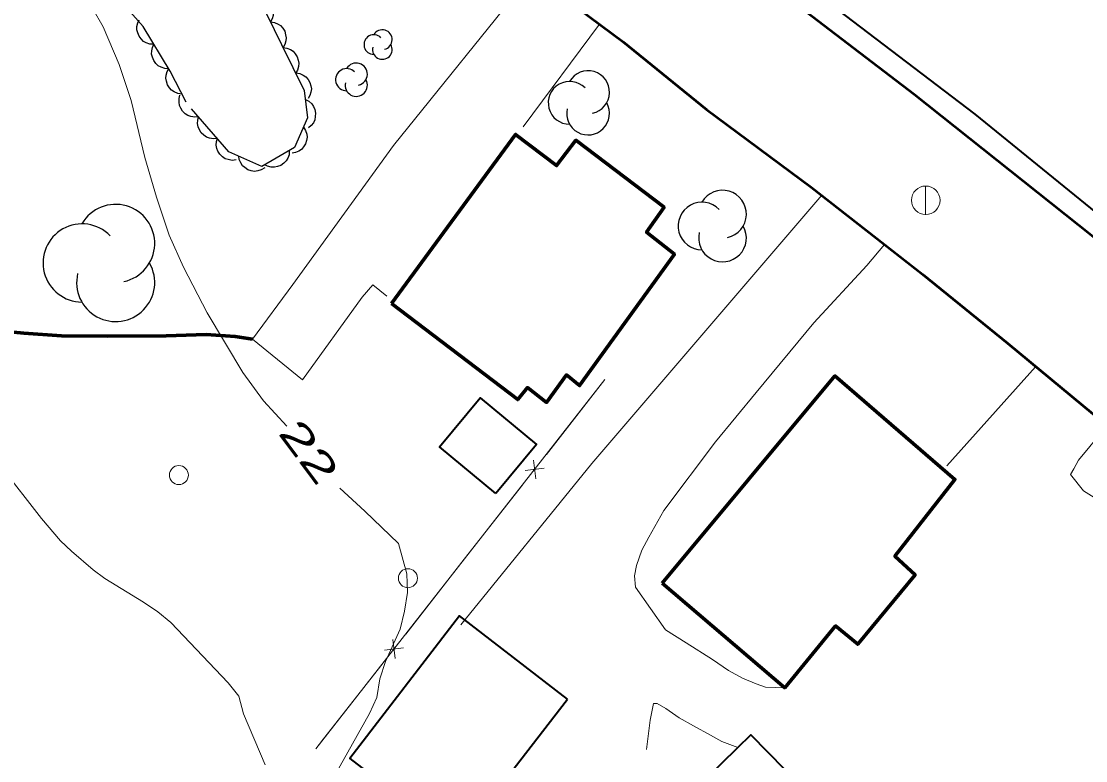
# Model space of a CAD drawing. Extents: x 356765 to 358572, y 5103174 to 5104650.
# Drawn here: x 357573.2 to 357629.2, y 5103650.7 to 5103689.6 of the extents above; entities that cross this region are included whole.
import ezdxf
from ezdxf.enums import TextEntityAlignment as Align

# ---------------------------------------------------------------- set-up
doc = ezdxf.new("R2010")
doc.units = 0
doc.header["$LTSCALE"] = 0.6
doc.linetypes.add('DOT_DASHED', pattern=[7.7, 5, -1.2, 0.3, -1.2])
doc.linetypes.add('LONG_DASHED', pattern=[7.5, 6, -1.5])
for name, color, linetype, lineweight in [('19', 7, 'Continuous', 13), ('2', 7, 'Continuous', 13), ('21', 7, 'Continuous', 53), ('22', 7, 'Continuous', 35), ('31', 7, 'Continuous', 70), ('36', 7, 'Continuous', 13), ('37', 7, 'Continuous', 13), ('44', 7, 'Continuous', 25)]:
    doc.layers.add(name, color=color, linetype=linetype, lineweight=lineweight)

msp = doc.modelspace()

# ---------------------------------------------------------------- linework, layer by layer
at = {"layer": '19'}
for p, q in [((357603.65, 5103689.44), (357599.62, 5103684.05)), ((357621.91, 5103666.22), (357626.58, 5103671.42))]:
    msp.add_line(p, q, dxfattribs=at)
for points in [[(357600.09, 5103692.09), (357592.81, 5103683.07), (357587.51, 5103675.75), (357585.39, 5103672.87), (357588.01, 5103670.74), (357591.15, 5103675.08), (357591.71, 5103675.74), (357592.45, 5103675.14)], [(357615.33, 5103680.45), (357603.23, 5103666.34), (357596.34, 5103657.85)], [(357618.63, 5103677.86), (357617.7, 5103676.76), (357614.92, 5103673.73), (357611.89, 5103670.07), (357609.75, 5103667.48), (357607.03, 5103663.87), (357606.24, 5103662.46), (357605.86, 5103661.79), (357605.59, 5103660.97), (357605.49, 5103660.44), (357605.54, 5103659.83), (357607.12, 5103657.59), (357608.2, 5103656.9), (357609.58, 5103656.03), (357610.43, 5103655.46), (357611.17, 5103655.05), (357611.89, 5103654.75), (357612.38, 5103654.57), (357613.39, 5103654.55)], [(357630.35, 5103668.35), (357629.44, 5103667.24), (357628.84, 5103666.51), (357628.59, 5103666.06), (357628.42, 5103665.77), (357629.11, 5103664.9), (357630.56, 5103663.99), (357630.72, 5103664.1), (357630.99, 5103664.24), (357631.65, 5103665.23), (357632.63, 5103666.4)], [(357610.92, 5103651.4), (357610.07, 5103651.72), (357609.48, 5103652.05), (357608.58, 5103652.55), (357607.84, 5103652.97), (357607.13, 5103653.46), (357606.68, 5103653.71), (357606.49, 5103653.72), (357606.3, 5103652.85), (357606.12, 5103651.3)]]:
    msp.add_lwpolyline(points, dxfattribs=at)
at = {"layer": '2'}
for points in [[(357587.19, 5103668.3), (357585.97, 5103669.63), (357584.88, 5103671.12), (357583.01, 5103674.26), (357581.75, 5103676.67), (357581, 5103678.34), (357580.34, 5103680.34), (357579.73, 5103682.44), (357579.01, 5103685.43), (357578.38, 5103687.33), (357577.53, 5103689.3), (357576.99, 5103690.25)], [(357586.06, 5103650.5), (357584.92, 5103653.17), (357584.66, 5103654.1), (357584.11, 5103654.8), (357581.09, 5103657.97), (357580.4, 5103658.54), (357579.66, 5103659.05), (357577.61, 5103660.3), (357577.01, 5103660.75), (357575.86, 5103661.73), (357575.29, 5103662.28), (357574.29, 5103663.44), (357572.13, 5103666.22)], [(357587.96, 5103646.82), (357591.54, 5103653.19), (357591.92, 5103654.04), (357592.08, 5103655.02), (357592.39, 5103655.92), (357593.15, 5103657.63), (357593.39, 5103658.57), (357593.54, 5103659.55), (357593.51, 5103660.54), (357593.06, 5103662.13), (357591.3, 5103663.84), (357589.98, 5103665.05)]]:
    msp.add_lwpolyline(points, dxfattribs=at)
at = {"layer": '21'}
for points in [[(357597.8, 5103693.8), (357604.89, 5103688.51), (357609.27, 5103684.96), (357614.77, 5103680.88), (357618.63, 5103677.86), (357620.65, 5103676.28), (357625.11, 5103672.66), (357629.6, 5103668.96), (357630.35, 5103668.35), (357631.55, 5103667.41), (357632.63, 5103666.4), (357636.95, 5103662.44), (357642.39, 5103657.42), (357648.4, 5103651.88), (357652.86, 5103647.7), (357660.15, 5103641.04), (357668.64, 5103633.26), (357674.75, 5103627.69), (357683.46, 5103619.66), (357688.82, 5103614.49), (357695.55, 5103608.21), (357701.4, 5103602.98), (357707.92, 5103596.9)], [(357609.42, 5103694), (357620.2, 5103685.76), (357630.29, 5103677.74), (357638.22, 5103670.75), (357649.79, 5103660.22), (357666.81, 5103644.4), (357691.49, 5103621.57), (357705.7, 5103608.53), (357720.27, 5103594.97), (357725.87, 5103589.74), (357737.61, 5103580.01), (357753.29, 5103566.65), (357772.09, 5103550.34), (357790.98, 5103533.8), (357803.11, 5103523.29), (357815.96, 5103512.34), (357841.89, 5103502.09), (357843.77, 5103501.5), (357845.45, 5103501.88), (357846.53, 5103502.66), (357866.19, 5103521.97)]]:
    msp.add_lwpolyline(points, dxfattribs=at)
at = {"layer": '22'}
msp.add_lwpolyline([(357610.19, 5103694.78), (357623.39, 5103684.71), (357633.04, 5103676.88), (357640.64, 5103670.23), (357649.82, 5103661.72), (357659.7, 5103652.78)], dxfattribs=at)
at = {"layer": '22', "linetype": 'LONG_DASHED', "lineweight": 70}
msp.add_lwpolyline([(357585.39, 5103672.87), (357584.48, 5103673.02), (357582.95, 5103673.12), (357580.84, 5103673.05), (357577.78, 5103673.03), (357575.33, 5103673.06), (357573.35, 5103673.19), (357569.8, 5103673.54), (357568.62, 5103673.71), (357567.22, 5103674), (357565.74, 5103674.34), (357564.38, 5103674.71), (357562.13, 5103675.57), (357557.66, 5103677.38), (357556.05, 5103678.18), (357553.84, 5103679.31), (357551.09, 5103680.82), (357548.78, 5103682.11), (357547.03, 5103683.18), (357544.91, 5103684.46), (357542.78, 5103685.74), (357540.55, 5103687.17), (357537.33, 5103689.29)], dxfattribs=at)
at = {"layer": '31'}
for points in [[(357592.7, 5103674.76), (357599.34, 5103669.7), (357599.85, 5103670.33), (357600.86, 5103669.55), (357601.9, 5103671), (357602.59, 5103670.44), (357607.58, 5103677.34), (357606.12, 5103678.5), (357607.04, 5103679.82), (357602.4, 5103683.34), (357601.38, 5103682.01), (357599.23, 5103683.65), (357592.7, 5103674.76)], [(357606.94, 5103660.04), (357616.03, 5103670.95), (357622.34, 5103665.5), (357619.18, 5103661.46), (357620.24, 5103660.48), (357617.23, 5103656.83), (357616.06, 5103657.8), (357613.39, 5103654.55), (357606.94, 5103660.04)]]:
    msp.add_lwpolyline(points, close=True, dxfattribs=at)
at = {"layer": '31', "lineweight": 35}
for points in [[(357598.18, 5103664.76), (357595.22, 5103667.22), (357597.36, 5103669.8), (357600.32, 5103667.34), (357598.18, 5103664.76)], [(357601.95, 5103653.95), (357596.28, 5103658.32), (357590.51, 5103650.82), (357596.18, 5103646.46), (357601.95, 5103653.95)], [(357620.04, 5103638.04), (357613.64, 5103644.54), (357613.07, 5103643.97), (357608.29, 5103648.82), (357610.92, 5103651.4), (357611.6, 5103652.07), (357616.03, 5103647.57), (357618.13, 5103649.63), (357624.87, 5103642.79), (357620.04, 5103638.04)]]:
    msp.add_lwpolyline(points, close=True, dxfattribs=at)
at = {"layer": '36'}
msp.add_line((357620.8, 5103679.42), (357620.8, 5103680.92), dxfattribs=at)
for centre, radius in [((357620.8055, 5103680.1813), 0.75), ((357581.5148, 5103665.7306), 0.5), ((357593.5638, 5103660.3071), 0.5)]:
    msp.add_circle(centre, radius, dxfattribs=at)
at = {"layer": '37'}
for p, q in [((357603.93, 5103670.75), (357588.72, 5103651.33)), ((357603.93, 5103670.75), (357600.85, 5103666.81)), ((357600.17, 5103666.52), (357600.29, 5103665.53)), ((357599.73, 5103665.97), (357600.73, 5103666.09)), ((357599.61, 5103665.24), (357596.53, 5103661.3)), ((357596.53, 5103661.3), (357593.45, 5103657.37)), ((357592.33, 5103656.52), (357593.33, 5103656.64)), ((357592.77, 5103657.08), (357592.89, 5103656.08)), ((357592.21, 5103655.79), (357589.13, 5103651.86)), ((357589.13, 5103651.86), (357588.72, 5103651.33))]:
    msp.add_line(p, q, dxfattribs=at)
at = {"layer": '44', "linetype": 'DOT_DASHED'}
msp.add_lwpolyline([(357585.73, 5103690.79), (357586.92, 5103688.38), (357588.11, 5103685.96), (357588.28, 5103684.51), (357587.6, 5103682.95), (357585.87, 5103681.96), (357584.15, 5103682.73), (357581.89, 5103685.34), (357581.05, 5103686.98), (357579.63, 5103689.33), (357575.92, 5103693.53)], dxfattribs=at)
at = {"layer": '44'}
for points in [[(357585.67, 5103690.91), (357585.88, 5103690.88), (357586.06, 5103690.8), (357586.2, 5103690.71), (357586.32, 5103690.58), (357586.41, 5103690.42), (357586.47, 5103690.24), (357586.5, 5103690.08), (357586.48, 5103689.9), (357586.42, 5103689.72), (357586.33, 5103689.57)], [(357580.2, 5103688.39), (357579.99, 5103688.4), (357579.8, 5103688.47), (357579.65, 5103688.54), (357579.53, 5103688.67), (357579.42, 5103688.81), (357579.35, 5103688.99), (357579.3, 5103689.15), (357579.31, 5103689.33), (357579.35, 5103689.51), (357579.42, 5103689.67)], [(357586.33, 5103689.57), (357586.54, 5103689.54), (357586.73, 5103689.45), (357586.86, 5103689.37), (357586.98, 5103689.23), (357587.08, 5103689.08), (357587.13, 5103688.89), (357587.16, 5103688.73), (357587.14, 5103688.56), (357587.09, 5103688.38), (357587, 5103688.22)], [(357580.98, 5103687.1), (357580.77, 5103687.11), (357580.58, 5103687.18), (357580.43, 5103687.26), (357580.3, 5103687.38), (357580.19, 5103687.53), (357580.12, 5103687.71), (357580.08, 5103687.87), (357580.09, 5103688.04), (357580.12, 5103688.22), (357580.2, 5103688.39)], [(357587, 5103688.22), (357587.2, 5103688.19), (357587.39, 5103688.11), (357587.53, 5103688.02), (357587.64, 5103687.89), (357587.74, 5103687.73), (357587.79, 5103687.55), (357587.82, 5103687.39), (357587.8, 5103687.21), (357587.75, 5103687.03), (357587.66, 5103686.88)], [(357581.67, 5103685.77), (357581.46, 5103685.8), (357581.27, 5103685.88), (357581.13, 5103685.97), (357581.02, 5103686.1), (357580.92, 5103686.25), (357580.86, 5103686.44), (357580.83, 5103686.6), (357580.85, 5103686.77), (357580.9, 5103686.95), (357580.98, 5103687.11)], [(357587.66, 5103686.88), (357587.87, 5103686.85), (357588.05, 5103686.76), (357588.19, 5103686.67), (357588.31, 5103686.54), (357588.4, 5103686.38), (357588.46, 5103686.2), (357588.49, 5103686.04), (357588.46, 5103685.86), (357588.41, 5103685.69), (357588.32, 5103685.53)], [(357582.55, 5103684.57), (357582.35, 5103684.55), (357582.15, 5103684.59), (357581.99, 5103684.64), (357581.84, 5103684.73), (357581.71, 5103684.86), (357581.61, 5103685.03), (357581.54, 5103685.17), (357581.52, 5103685.35), (357581.52, 5103685.53), (357581.57, 5103685.71)], [(357588.17, 5103685.48), (357588.35, 5103685.39), (357588.5, 5103685.25), (357588.6, 5103685.12), (357588.66, 5103684.95), (357588.7, 5103684.77), (357588.69, 5103684.58), (357588.67, 5103684.42), (357588.59, 5103684.26), (357588.48, 5103684.11), (357588.34, 5103683.99)], [(357583.54, 5103683.44), (357583.33, 5103683.42), (357583.13, 5103683.45), (357582.97, 5103683.5), (357582.82, 5103683.6), (357582.69, 5103683.73), (357582.59, 5103683.89), (357582.52, 5103684.04), (357582.5, 5103684.22), (357582.51, 5103684.4), (357582.55, 5103684.57)], [(357588.07, 5103684.03), (357588.18, 5103683.86), (357588.24, 5103683.66), (357588.26, 5103683.5), (357588.23, 5103683.32), (357588.18, 5103683.15), (357588.07, 5103682.99), (357587.97, 5103682.86), (357587.82, 5103682.77), (357587.65, 5103682.69), (357587.47, 5103682.66)], [(357584.52, 5103682.31), (357584.31, 5103682.28), (357584.11, 5103682.32), (357583.95, 5103682.37), (357583.81, 5103682.47), (357583.67, 5103682.6), (357583.57, 5103682.76), (357583.51, 5103682.91), (357583.48, 5103683.08), (357583.49, 5103683.27), (357583.54, 5103683.44)], [(357586.03, 5103681.89), (357585.85, 5103681.78), (357585.66, 5103681.73), (357585.49, 5103681.7), (357585.32, 5103681.73), (357585.14, 5103681.79), (357584.99, 5103681.9), (357584.86, 5103682), (357584.77, 5103682.15), (357584.69, 5103682.32), (357584.66, 5103682.5)], [(357587.32, 5103682.79), (357587.31, 5103682.58), (357587.24, 5103682.39), (357587.16, 5103682.25), (357587.03, 5103682.13), (357586.88, 5103682.02), (357586.7, 5103681.96), (357586.54, 5103681.92), (357586.37, 5103681.93), (357586.18, 5103681.97), (357586.02, 5103682.05)]]:
    msp.add_lwpolyline(points, dxfattribs=at)
for centre, radius, start, end in [((357592.2164, 5103688.6308), 0.5181, 282.26917, 149.72626), ((357591.7709, 5103688.3718), 0.5181, 44.11537, 269.80396), ((357592.2164, 5103688.1127), 0.5181, 166.93686, 29.62122), ((357590.3413, 5103686.5233), 0.5849, 44.11537, 269.80396), ((357590.8443, 5103686.8157), 0.5849, 282.26917, 149.72626), ((357603.0402, 5103685.8684), 1.1257, 282.26917, 149.72626), ((357590.8443, 5103686.2308), 0.5849, 166.93686, 29.62122), ((357602.0721, 5103685.3056), 1.1257, 44.11537, 269.80396), ((357603.0402, 5103684.7427), 1.1257, 166.93686, 29.62122), ((357610.1139, 5103679.4557), 1.2544, 282.26917, 149.72626), ((357578.1882, 5103677.9141), 2.0548, 282.26917, 149.72626), ((357609.0352, 5103678.8285), 1.2544, 44.11537, 269.80396), ((357576.4211, 5103676.8867), 2.0548, 44.11537, 269.80396), ((357610.1139, 5103678.2013), 1.2544, 166.93686, 29.62122), ((357578.1882, 5103675.8593), 2.0548, 166.93686, 29.62122)]:
    msp.add_arc(centre, radius, start, end, dxfattribs=at)

# ---------------------------------------------------------------- texts
at = {"layer": '2', "width": 1.6}
msp.add_text('22', height=1.5, rotation=306.736, dxfattribs=at).set_placement((357587.7583, 5103666.5086), align=Align.CENTER)

doc.saveas('drawing.dxf')
